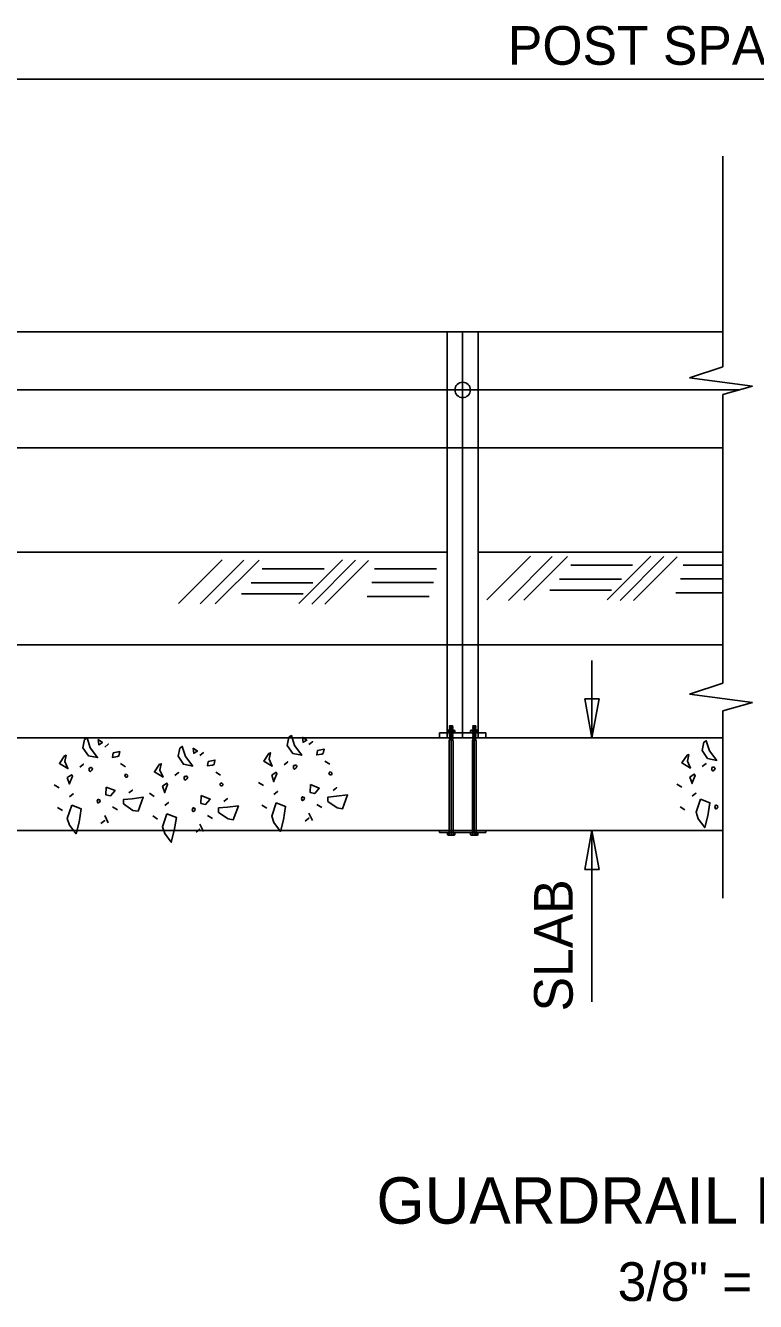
# Model space of a CAD drawing. Extents: x 0 to 90.7, y 0 to 62.8.
# Drawn here: x 18.44 to 26.31, y 29.79 to 43.55 of the extents above; entities that cross this region are included whole.
import ezdxf

# ---------------------------------------------------------------- set-up
doc = ezdxf.new("R2010")
doc.units = 0
for name, color, linetype in [('BRDG_ANNO_General-Notes', 7, 'Continuous'), ('BRDG_BASE_Ground-Lines', 7, 'Continuous'), ('BRDG_BASE_Hidden-Line', 7, 'Continuous'), ('BRDG_BASE_Obj-Line', 7, 'Continuous'), ('BRDG_BASE_Pattern', 7, 'Continuous')]:
    doc.layers.add(name, color=color, linetype=linetype)

msp = doc.modelspace()

# ---------------------------------------------------------------- linework, layer by layer
at = {"layer": 'BRDG_ANNO_General-Notes'}
for p, q in [((16.903, 42.967), (35.653, 42.967)), ((24.548, 35.866), (24.548, 36.697)), ((24.469, 36.286), (24.627, 36.286)), ((24.548, 35.866), (24.469, 36.286)), ((24.627, 36.286), (24.548, 35.866)), ((24.469, 34.446), (24.548, 34.866)), ((24.548, 33.018), (24.548, 34.866)), ((24.548, 34.866), (24.627, 34.446)), ((24.627, 34.446), (24.469, 34.446))]:
    msp.add_line(p, q, dxfattribs=at)
at = {"layer": 'BRDG_BASE_Ground-Lines'}
for p, q in [((20.559, 37.784), (20.087, 37.312)), ((20.791, 37.779), (20.32, 37.308)), ((20.957, 37.781), (20.485, 37.31)), ((21.856, 37.784), (21.385, 37.312)), ((21.996, 37.779), (21.525, 37.307)), ((22.138, 37.778), (21.667, 37.307)), ((23.886, 37.823), (23.415, 37.352)), ((24.119, 37.818), (23.647, 37.347)), ((24.284, 37.82), (23.813, 37.349)), ((24.319, 37.727), (24.985, 37.727)), ((25.184, 37.823), (24.712, 37.352)), ((25.324, 37.818), (24.852, 37.347)), ((25.466, 37.817), (24.994, 37.346)), ((25.531, 37.727), (25.958, 37.727)), ((20.991, 37.688), (21.658, 37.688)), ((22.203, 37.688), (22.87, 37.688)), ((24.198, 37.574), (24.865, 37.574)), ((25.501, 37.579), (25.958, 37.579)), ((20.871, 37.535), (21.537, 37.535)), ((22.173, 37.54), (22.84, 37.54)), ((24.093, 37.456), (24.76, 37.456)), ((25.451, 37.429), (25.958, 37.429)), ((20.766, 37.417), (21.432, 37.417)), ((22.123, 37.39), (22.79, 37.39))]:
    msp.add_line(p, q, dxfattribs=at)
at = {"layer": 'BRDG_BASE_Hidden-Line'}
for p, q in [((23.029, 35.968), (23.029, 35.917)), ((23.029, 35.948), (23.029, 35.918)), ((23.279, 35.968), (23.279, 35.917)), ((23.279, 35.948), (23.279, 35.918)), ((23.029, 34.814), (23.029, 34.844)), ((23.279, 34.814), (23.279, 34.844))]:
    msp.add_line(p, q, dxfattribs=at)
at = {"layer": 'BRDG_BASE_Obj-Line'}
for p, q in [((25.958, 39.865), (25.958, 42.137)), ((6.426, 40.241), (25.958, 40.241)), ((22.987, 40.241), (22.987, 38.991)), ((23.153, 35.866), (23.153, 40.241)), ((23.32, 40.241), (23.32, 38.991)), ((25.958, 39.865), (25.598, 39.748)), ((25.598, 39.748), (26.28, 39.657)), ((26.28, 39.657), (25.958, 39.565)), ((6.426, 39.616), (26.143, 39.616)), ((23.153, 39.616), (23.153, 39.616)), ((25.958, 36.454), (25.958, 39.565)), ((6.426, 38.991), (25.958, 38.991)), ((22.987, 35.866), (22.987, 38.991)), ((23.32, 35.866), (23.32, 38.991)), ((17.07, 37.866), (22.987, 37.866)), ((23.32, 37.866), (25.958, 37.866)), ((13.903, 36.866), (25.958, 36.866)), ((25.958, 36.454), (25.598, 36.337)), ((25.598, 36.337), (26.28, 36.247)), ((26.28, 36.247), (25.958, 36.155)), ((25.958, 34.137), (25.958, 36.155)), ((22.903, 35.918), (23.403, 35.918)), ((22.903, 35.866), (22.903, 35.918)), ((22.989, 35.92), (22.989, 35.945)), ((23.067, 35.918), (22.991, 35.918)), ((23.059, 35.948), (22.999, 35.948)), ((23.014, 35.994), (23.009, 35.991)), ((23.044, 35.994), (23.009, 35.991)), ((23.014, 35.987), (23.009, 35.991)), ((23.014, 35.987), (23.009, 35.984)), ((23.049, 35.987), (23.009, 35.984)), ((23.014, 35.981), (23.009, 35.984)), ((23.014, 35.981), (23.009, 35.977)), ((23.049, 35.981), (23.009, 35.977)), ((23.014, 35.974), (23.009, 35.977)), ((23.014, 35.974), (23.009, 35.971)), ((23.049, 35.974), (23.009, 35.971)), ((23.014, 35.968), (23.009, 35.971)), ((23.014, 35.968), (23.009, 35.964)), ((23.049, 35.968), (23.009, 35.964)), ((23.014, 35.961), (23.009, 35.964)), ((23.014, 35.961), (23.009, 35.958)), ((23.049, 35.961), (23.009, 35.958)), ((23.014, 35.954), (23.009, 35.958)), ((23.014, 35.954), (23.009, 35.951)), ((23.049, 35.954), (23.009, 35.951)), ((23.014, 35.948), (23.009, 35.951)), ((23.014, 35.948), (23.009, 35.944)), ((23.049, 35.948), (23.009, 35.944)), ((23.009, 35.918), (23.009, 35.945)), ((23.014, 35.941), (23.009, 35.944)), ((23.014, 35.941), (23.009, 35.938)), ((23.049, 35.941), (23.009, 35.938)), ((23.014, 35.935), (23.009, 35.938)), ((23.014, 35.935), (23.009, 35.931)), ((23.049, 35.935), (23.009, 35.931)), ((23.014, 35.928), (23.009, 35.931)), ((23.014, 35.928), (23.009, 35.925)), ((23.049, 35.928), (23.009, 35.925)), ((23.014, 35.921), (23.009, 35.925)), ((23.014, 35.921), (23.009, 35.918)), ((23.049, 35.921), (23.009, 35.918)), ((23.014, 35.915), (23.009, 35.918)), ((23.014, 35.915), (23.009, 35.911)), ((23.049, 35.915), (23.009, 35.911)), ((23.014, 35.908), (23.009, 35.911)), ((23.044, 35.994), (23.014, 35.994)), ((23.044, 35.991), (23.014, 35.987)), ((23.044, 35.984), (23.014, 35.981)), ((23.044, 35.977), (23.014, 35.974)), ((23.044, 35.971), (23.014, 35.968)), ((23.044, 35.964), (23.014, 35.961)), ((23.044, 35.958), (23.014, 35.954)), ((23.044, 35.951), (23.014, 35.948)), ((23.044, 35.944), (23.014, 35.941)), ((23.044, 35.938), (23.014, 35.935)), ((23.044, 35.931), (23.014, 35.928)), ((23.044, 35.925), (23.014, 35.921)), ((23.044, 35.918), (23.014, 35.915)), ((23.044, 35.911), (23.014, 35.908)), ((23.028, 34.845), (23.028, 35.918)), ((23.044, 35.994), (23.046, 35.992)), ((23.044, 35.991), (23.046, 35.992)), ((23.044, 35.991), (23.049, 35.987)), ((23.044, 35.984), (23.049, 35.987)), ((23.044, 35.984), (23.049, 35.981)), ((23.044, 35.977), (23.049, 35.981)), ((23.044, 35.977), (23.049, 35.974)), ((23.044, 35.971), (23.049, 35.974)), ((23.044, 35.971), (23.049, 35.968)), ((23.044, 35.964), (23.049, 35.968)), ((23.044, 35.964), (23.049, 35.961)), ((23.044, 35.958), (23.049, 35.961)), ((23.044, 35.958), (23.049, 35.954)), ((23.044, 35.951), (23.049, 35.954)), ((23.044, 35.951), (23.049, 35.948)), ((23.044, 35.944), (23.049, 35.948)), ((23.044, 35.944), (23.049, 35.941)), ((23.044, 35.938), (23.049, 35.941)), ((23.044, 35.938), (23.049, 35.935)), ((23.044, 35.931), (23.049, 35.935)), ((23.044, 35.931), (23.049, 35.928)), ((23.044, 35.925), (23.049, 35.928)), ((23.044, 35.925), (23.049, 35.921)), ((23.044, 35.918), (23.049, 35.921)), ((23.044, 35.918), (23.049, 35.915)), ((23.044, 35.911), (23.049, 35.915)), ((23.044, 35.911), (23.049, 35.908)), ((23.049, 35.918), (23.049, 35.945)), ((23.069, 35.92), (23.069, 35.945)), ((23.239, 35.92), (23.239, 35.945)), ((23.317, 35.918), (23.241, 35.918)), ((23.309, 35.948), (23.249, 35.948)), ((23.264, 35.994), (23.259, 35.991)), ((23.294, 35.994), (23.259, 35.991)), ((23.264, 35.987), (23.259, 35.991)), ((23.264, 35.987), (23.259, 35.984)), ((23.299, 35.987), (23.259, 35.984)), ((23.264, 35.981), (23.259, 35.984)), ((23.264, 35.981), (23.259, 35.977)), ((23.299, 35.981), (23.259, 35.977)), ((23.264, 35.974), (23.259, 35.977)), ((23.264, 35.974), (23.259, 35.971)), ((23.299, 35.974), (23.259, 35.971)), ((23.264, 35.968), (23.259, 35.971)), ((23.264, 35.968), (23.259, 35.964)), ((23.299, 35.968), (23.259, 35.964)), ((23.264, 35.961), (23.259, 35.964)), ((23.264, 35.961), (23.259, 35.958)), ((23.299, 35.961), (23.259, 35.958)), ((23.264, 35.954), (23.259, 35.958)), ((23.264, 35.954), (23.259, 35.951)), ((23.299, 35.954), (23.259, 35.951)), ((23.264, 35.948), (23.259, 35.951)), ((23.264, 35.948), (23.259, 35.944)), ((23.299, 35.948), (23.259, 35.944)), ((23.259, 35.918), (23.259, 35.945)), ((23.264, 35.941), (23.259, 35.944)), ((23.264, 35.941), (23.259, 35.938)), ((23.299, 35.941), (23.259, 35.938)), ((23.264, 35.935), (23.259, 35.938)), ((23.264, 35.935), (23.259, 35.931)), ((23.299, 35.935), (23.259, 35.931)), ((23.264, 35.928), (23.259, 35.931)), ((23.264, 35.928), (23.259, 35.925)), ((23.299, 35.928), (23.259, 35.925)), ((23.264, 35.921), (23.259, 35.925)), ((23.264, 35.921), (23.259, 35.918)), ((23.299, 35.921), (23.259, 35.918)), ((23.264, 35.915), (23.259, 35.918)), ((23.264, 35.915), (23.259, 35.911)), ((23.299, 35.915), (23.259, 35.911)), ((23.264, 35.908), (23.259, 35.911)), ((23.294, 35.994), (23.264, 35.994)), ((23.294, 35.991), (23.264, 35.987)), ((23.294, 35.984), (23.264, 35.981)), ((23.294, 35.977), (23.264, 35.974)), ((23.294, 35.971), (23.264, 35.968)), ((23.294, 35.964), (23.264, 35.961)), ((23.294, 35.958), (23.264, 35.954)), ((23.294, 35.951), (23.264, 35.948)), ((23.294, 35.944), (23.264, 35.941)), ((23.294, 35.938), (23.264, 35.935)), ((23.294, 35.931), (23.264, 35.928)), ((23.294, 35.925), (23.264, 35.921)), ((23.294, 35.918), (23.264, 35.915)), ((23.294, 35.911), (23.264, 35.908)), ((23.278, 34.845), (23.278, 35.918)), ((23.294, 35.994), (23.296, 35.992)), ((23.294, 35.991), (23.296, 35.992)), ((23.294, 35.991), (23.299, 35.987)), ((23.294, 35.984), (23.299, 35.987)), ((23.294, 35.984), (23.299, 35.981)), ((23.294, 35.977), (23.299, 35.981)), ((23.294, 35.977), (23.299, 35.974)), ((23.294, 35.971), (23.299, 35.974)), ((23.294, 35.971), (23.299, 35.968)), ((23.294, 35.964), (23.299, 35.968)), ((23.294, 35.964), (23.299, 35.961)), ((23.294, 35.958), (23.299, 35.961)), ((23.294, 35.958), (23.299, 35.954)), ((23.294, 35.951), (23.299, 35.954)), ((23.294, 35.951), (23.299, 35.948)), ((23.294, 35.944), (23.299, 35.948)), ((23.294, 35.944), (23.299, 35.941)), ((23.294, 35.938), (23.299, 35.941)), ((23.294, 35.938), (23.299, 35.935)), ((23.294, 35.931), (23.299, 35.935)), ((23.294, 35.931), (23.299, 35.928)), ((23.294, 35.925), (23.299, 35.928)), ((23.294, 35.925), (23.299, 35.921)), ((23.294, 35.918), (23.299, 35.921)), ((23.294, 35.918), (23.299, 35.915)), ((23.294, 35.911), (23.299, 35.915)), ((23.294, 35.911), (23.299, 35.908)), ((23.299, 35.918), (23.299, 35.945)), ((23.318, 35.92), (23.318, 35.945)), ((23.403, 35.866), (23.403, 35.918)), ((13.903, 35.866), (25.958, 35.866)), ((23.014, 35.908), (23.009, 35.905)), ((23.049, 35.908), (23.009, 35.905)), ((23.014, 35.902), (23.009, 35.905)), ((23.014, 35.902), (23.009, 35.898)), ((23.049, 35.902), (23.009, 35.898)), ((23.014, 35.895), (23.009, 35.898)), ((23.014, 35.895), (23.009, 35.892)), ((23.049, 35.895), (23.009, 35.892)), ((23.014, 35.888), (23.009, 35.892)), ((23.014, 35.888), (23.009, 35.885)), ((23.049, 35.888), (23.009, 35.885)), ((23.014, 35.882), (23.009, 35.885)), ((23.014, 35.882), (23.009, 35.878)), ((23.049, 35.882), (23.009, 35.878)), ((23.014, 35.875), (23.009, 35.878)), ((23.014, 35.875), (23.009, 35.872)), ((23.049, 35.875), (23.009, 35.872)), ((23.014, 35.869), (23.009, 35.872)), ((23.014, 35.869), (23.009, 35.865)), ((23.049, 35.869), (23.009, 35.865)), ((23.014, 35.862), (23.009, 35.865)), ((23.014, 35.862), (23.009, 35.859)), ((23.049, 35.862), (23.009, 35.859)), ((23.014, 35.855), (23.009, 35.859)), ((23.014, 35.855), (23.009, 35.852)), ((23.049, 35.855), (23.009, 35.852)), ((23.014, 35.849), (23.009, 35.852)), ((23.014, 35.849), (23.009, 35.845)), ((23.049, 35.849), (23.009, 35.845)), ((23.014, 35.842), (23.009, 35.845)), ((23.014, 35.842), (23.009, 35.839)), ((23.049, 35.842), (23.009, 35.839)), ((23.009, 35.839), (23.009, 34.844)), ((23.044, 35.905), (23.014, 35.902)), ((23.044, 35.898), (23.014, 35.895)), ((23.044, 35.892), (23.014, 35.888)), ((23.044, 35.885), (23.014, 35.882)), ((23.044, 35.878), (23.014, 35.875)), ((23.044, 35.872), (23.014, 35.869)), ((23.044, 35.865), (23.014, 35.862)), ((23.044, 35.859), (23.014, 35.855)), ((23.044, 35.852), (23.014, 35.849)), ((23.044, 35.845), (23.014, 35.842)), ((23.044, 35.839), (23.029, 35.837)), ((23.044, 35.905), (23.049, 35.908)), ((23.044, 35.905), (23.049, 35.902)), ((23.044, 35.898), (23.049, 35.902)), ((23.044, 35.898), (23.049, 35.895)), ((23.044, 35.892), (23.049, 35.895)), ((23.044, 35.892), (23.049, 35.888)), ((23.044, 35.885), (23.049, 35.888)), ((23.044, 35.885), (23.049, 35.882)), ((23.044, 35.878), (23.049, 35.882)), ((23.044, 35.878), (23.049, 35.875)), ((23.044, 35.872), (23.049, 35.875)), ((23.044, 35.872), (23.049, 35.869)), ((23.044, 35.865), (23.049, 35.869)), ((23.044, 35.865), (23.049, 35.862)), ((23.044, 35.859), (23.049, 35.862)), ((23.044, 35.859), (23.049, 35.855)), ((23.044, 35.852), (23.049, 35.855)), ((23.044, 35.852), (23.049, 35.849)), ((23.044, 35.845), (23.049, 35.849)), ((23.044, 35.845), (23.049, 35.842)), ((23.044, 35.839), (23.049, 35.842)), ((23.044, 35.839), (23.049, 35.836)), ((23.049, 35.836), (23.049, 34.844)), ((23.264, 35.908), (23.259, 35.905)), ((23.299, 35.908), (23.259, 35.905)), ((23.264, 35.902), (23.259, 35.905)), ((23.264, 35.902), (23.259, 35.898)), ((23.299, 35.902), (23.259, 35.898)), ((23.264, 35.895), (23.259, 35.898)), ((23.264, 35.895), (23.259, 35.892)), ((23.299, 35.895), (23.259, 35.892)), ((23.264, 35.888), (23.259, 35.892)), ((23.264, 35.888), (23.259, 35.885)), ((23.299, 35.888), (23.259, 35.885)), ((23.264, 35.882), (23.259, 35.885)), ((23.264, 35.882), (23.259, 35.878)), ((23.299, 35.882), (23.259, 35.878)), ((23.264, 35.875), (23.259, 35.878)), ((23.264, 35.875), (23.259, 35.872)), ((23.299, 35.875), (23.259, 35.872)), ((23.264, 35.869), (23.259, 35.872)), ((23.264, 35.869), (23.259, 35.865)), ((23.299, 35.869), (23.259, 35.865)), ((23.264, 35.862), (23.259, 35.865)), ((23.264, 35.862), (23.259, 35.859)), ((23.299, 35.862), (23.259, 35.859)), ((23.264, 35.855), (23.259, 35.859)), ((23.264, 35.855), (23.259, 35.852)), ((23.299, 35.855), (23.259, 35.852)), ((23.264, 35.849), (23.259, 35.852)), ((23.264, 35.849), (23.259, 35.845)), ((23.299, 35.849), (23.259, 35.845)), ((23.264, 35.842), (23.259, 35.845)), ((23.264, 35.842), (23.259, 35.839)), ((23.299, 35.842), (23.259, 35.839)), ((23.259, 35.839), (23.259, 34.844)), ((23.294, 35.905), (23.264, 35.902)), ((23.294, 35.898), (23.264, 35.895)), ((23.294, 35.892), (23.264, 35.888)), ((23.294, 35.885), (23.264, 35.882)), ((23.294, 35.878), (23.264, 35.875)), ((23.294, 35.872), (23.264, 35.869)), ((23.294, 35.865), (23.264, 35.862)), ((23.294, 35.859), (23.264, 35.855)), ((23.294, 35.852), (23.264, 35.849)), ((23.294, 35.845), (23.264, 35.842)), ((23.294, 35.839), (23.279, 35.837)), ((23.294, 35.905), (23.299, 35.908)), ((23.294, 35.905), (23.299, 35.902)), ((23.294, 35.898), (23.299, 35.902)), ((23.294, 35.898), (23.299, 35.895)), ((23.294, 35.892), (23.299, 35.895)), ((23.294, 35.892), (23.299, 35.888)), ((23.294, 35.885), (23.299, 35.888)), ((23.294, 35.885), (23.299, 35.882)), ((23.294, 35.878), (23.299, 35.882)), ((23.294, 35.878), (23.299, 35.875)), ((23.294, 35.872), (23.299, 35.875)), ((23.294, 35.872), (23.299, 35.869)), ((23.294, 35.865), (23.299, 35.869)), ((23.294, 35.865), (23.299, 35.862)), ((23.294, 35.859), (23.299, 35.862)), ((23.294, 35.859), (23.299, 35.855)), ((23.294, 35.852), (23.299, 35.855)), ((23.294, 35.852), (23.299, 35.849)), ((23.294, 35.845), (23.299, 35.849)), ((23.294, 35.845), (23.299, 35.842)), ((23.294, 35.839), (23.299, 35.842)), ((23.294, 35.839), (23.299, 35.836)), ((23.299, 35.836), (23.299, 34.844)), ((15.903, 34.866), (25.958, 34.866)), ((22.903, 34.866), (22.903, 34.845)), ((22.903, 34.845), (23.403, 34.845)), ((22.989, 34.842), (22.989, 34.818)), ((23.067, 34.844), (22.991, 34.844)), ((23.059, 34.814), (22.999, 34.814)), ((23.009, 34.844), (23.009, 34.818)), ((23.049, 34.844), (23.049, 34.818)), ((23.069, 34.842), (23.069, 34.818)), ((23.239, 34.842), (23.239, 34.818)), ((23.317, 34.844), (23.241, 34.844)), ((23.309, 34.814), (23.249, 34.814)), ((23.259, 34.844), (23.259, 34.818)), ((23.299, 34.844), (23.299, 34.818)), ((23.318, 34.842), (23.318, 34.818)), ((23.403, 34.845), (23.403, 34.866))]:
    msp.add_line(p, q, dxfattribs=at)
msp.add_circle((23.153, 39.616), 0.0833, dxfattribs=at)
for centre, radius, start, end in [((22.999, 35.933), 0.0157, 50.7833, 129.2167), ((22.991, 35.92), 0.00198, 180, 270), ((23.029, 35.893), 0.055, 68.9268, 111.0732), ((23.059, 35.933), 0.0157, 50.7833, 129.2167), ((23.067, 35.92), 0.00198, 270, 0), ((23.249, 35.933), 0.0157, 50.7833, 129.2167), ((23.241, 35.92), 0.00198, 180, 270), ((23.279, 35.893), 0.055, 68.9268, 111.0732), ((23.309, 35.933), 0.0157, 50.7833, 129.2167), ((23.316, 35.92), 0.00198, 270, 0), ((22.991, 34.842), 0.00198, 90, 180), ((22.999, 34.83), 0.0157, 230.7833, 309.2167), ((23.029, 34.869), 0.055, 248.9268, 291.0732), ((23.059, 34.83), 0.0157, 230.7833, 309.2167), ((23.067, 34.842), 0.00198, 0, 90), ((23.241, 34.842), 0.00198, 90, 180), ((23.249, 34.83), 0.0157, 230.7833, 309.2167), ((23.279, 34.869), 0.055, 248.9268, 291.0732), ((23.309, 34.83), 0.0157, 230.7833, 309.2167), ((23.316, 34.842), 0.00198, 0, 90)]:
    msp.add_arc(centre, radius, start, end, dxfattribs=at)
at = {"layer": 'BRDG_BASE_Pattern'}
for p, q in [((19.463, 35.586), (19.516, 35.553)), ((21.666, 35.612), (21.719, 35.579)), ((20.489, 35.494), (20.541, 35.461)), ((20.952, 35.384), (21.005, 35.351)), ((25.463, 35.364), (25.516, 35.331)), ((18.748, 35.358), (18.801, 35.325)), ((19.774, 35.266), (19.827, 35.233)), ((18.784, 35.114), (18.837, 35.081)), ((19.376, 35.12), (19.429, 35.087)), ((20.988, 35.14), (21.041, 35.107)), ((21.58, 35.146), (21.633, 35.113)), ((25.498, 35.12), (25.551, 35.087)), ((19.292, 35.026), (19.331, 34.947)), ((19.81, 35.022), (19.863, 34.989)), ((20.402, 35.028), (20.455, 34.995)), ((21.495, 35.052), (21.535, 34.973)), ((20.317, 34.934), (20.357, 34.855))]:
    msp.add_line(p, q, dxfattribs=at)
for points in [[(19.075, 35.846), (19.058, 35.757), (19.116, 35.671), (19.215, 35.651), (19.136, 35.756), (19.103, 35.864)], [(19.22, 35.845), (19.228, 35.79), (19.267, 35.813)], [(19.292, 35.765), (19.331, 35.797)], [(21.279, 35.872), (21.261, 35.783), (21.32, 35.697), (21.418, 35.677), (21.34, 35.782), (21.306, 35.889)], [(21.424, 35.871), (21.431, 35.816), (21.471, 35.839)], [(21.495, 35.791), (21.535, 35.823)], [(25.753, 35.816), (25.735, 35.727), (25.794, 35.64), (25.893, 35.621), (25.814, 35.725), (25.78, 35.833)], [(18.859, 35.671), (18.804, 35.588), (18.896, 35.533), (18.863, 35.608), (18.876, 35.677)], [(19.383, 35.701), (19.375, 35.654), (19.431, 35.662), (19.446, 35.67), (19.454, 35.717)], [(20.101, 35.754), (20.083, 35.666), (20.142, 35.579), (20.241, 35.559), (20.162, 35.664), (20.128, 35.772)], [(20.246, 35.753), (20.253, 35.698), (20.293, 35.722)], [(20.317, 35.673), (20.357, 35.705)], [(21.062, 35.697), (21.007, 35.614), (21.1, 35.559), (21.066, 35.634), (21.08, 35.703)], [(21.587, 35.727), (21.579, 35.68), (21.634, 35.688), (21.65, 35.696), (21.658, 35.743)], [(25.573, 35.677), (25.518, 35.594), (25.61, 35.539), (25.577, 35.614), (25.591, 35.683)], [(19.024, 35.549), (19.063, 35.581)], [(19.124, 35.539), (19.124, 35.51), (19.138, 35.5), (19.142, 35.504), (19.154, 35.516), (19.161, 35.531), (19.156, 35.539), (19.148, 35.543), (19.144, 35.543), (19.136, 35.541)], [(19.884, 35.579), (19.829, 35.497), (19.922, 35.441), (19.888, 35.516), (19.902, 35.585)], [(20.409, 35.609), (20.401, 35.562), (20.456, 35.57), (20.472, 35.578), (20.48, 35.625)], [(21.228, 35.575), (21.267, 35.607)], [(21.328, 35.565), (21.328, 35.535), (21.342, 35.526), (21.346, 35.53), (21.357, 35.542), (21.365, 35.557), (21.36, 35.565), (21.352, 35.569), (21.348, 35.569), (21.34, 35.567)], [(21.721, 35.498), (21.711, 35.477), (21.723, 35.465), (21.737, 35.465), (21.743, 35.471), (21.743, 35.483), (21.741, 35.488), (21.735, 35.494)], [(25.738, 35.555), (25.778, 35.586)], [(25.839, 35.545), (25.839, 35.515), (25.852, 35.506), (25.856, 35.51), (25.868, 35.521), (25.876, 35.537), (25.87, 35.545), (25.862, 35.549), (25.858, 35.549), (25.85, 35.547)], [(18.889, 35.436), (18.913, 35.365), (18.913, 35.373), (18.945, 35.452), (18.937, 35.467)], [(19.518, 35.472), (19.508, 35.451), (19.519, 35.439), (19.533, 35.439), (19.539, 35.445), (19.539, 35.457), (19.537, 35.462), (19.531, 35.468)], [(19.915, 35.344), (19.939, 35.273), (19.939, 35.281), (19.971, 35.36), (19.963, 35.375)], [(20.05, 35.457), (20.089, 35.489)], [(20.15, 35.447), (20.15, 35.418), (20.164, 35.408), (20.168, 35.412), (20.179, 35.424), (20.187, 35.439), (20.182, 35.447), (20.174, 35.451), (20.17, 35.451), (20.162, 35.449)], [(20.544, 35.38), (20.534, 35.359), (20.545, 35.347), (20.559, 35.347), (20.565, 35.353), (20.565, 35.365), (20.563, 35.37), (20.557, 35.377)], [(21.093, 35.462), (21.117, 35.391), (21.117, 35.399), (21.148, 35.478), (21.141, 35.493)], [(21.511, 35.36), (21.507, 35.276), (21.558, 35.264), (21.607, 35.321)], [(25.604, 35.442), (25.627, 35.371), (25.627, 35.379), (25.659, 35.458), (25.651, 35.473)], [(18.914, 35.228), (18.953, 35.26)], [(19.307, 35.334), (19.303, 35.25), (19.354, 35.238), (19.404, 35.295)], [(19.589, 35.208), (19.495, 35.2), (19.495, 35.153), (19.597, 35.082), (19.653, 35.074), (19.708, 35.223)], [(19.551, 35.27), (19.591, 35.301)], [(20.333, 35.243), (20.329, 35.158), (20.38, 35.146), (20.43, 35.203)], [(21.118, 35.254), (21.157, 35.286)], [(21.415, 35.209), (21.421, 35.189), (21.426, 35.189), (21.434, 35.191), (21.44, 35.197), (21.446, 35.209), (21.444, 35.221), (21.434, 35.223), (21.43, 35.227), (21.422, 35.227)], [(21.793, 35.234), (21.699, 35.226), (21.699, 35.179), (21.801, 35.108), (21.857, 35.1), (21.912, 35.249)], [(21.755, 35.296), (21.794, 35.327)], [(25.628, 35.234), (25.668, 35.266)], [(18.937, 35.137), (18.889, 34.995), (18.913, 34.924), (18.984, 34.83), (19.015, 34.956), (19.039, 35.098)], [(19.211, 35.183), (19.217, 35.163), (19.223, 35.163), (19.23, 35.166), (19.237, 35.171), (19.242, 35.183), (19.24, 35.195), (19.23, 35.197), (19.227, 35.201), (19.219, 35.201)], [(19.94, 35.136), (19.979, 35.168)], [(20.237, 35.091), (20.243, 35.071), (20.248, 35.071), (20.256, 35.074), (20.262, 35.079), (20.268, 35.091), (20.266, 35.103), (20.256, 35.105), (20.252, 35.109), (20.245, 35.109)], [(20.615, 35.116), (20.521, 35.108), (20.521, 35.061), (20.623, 34.99), (20.679, 34.982), (20.734, 35.131)], [(20.577, 35.178), (20.616, 35.209)], [(21.141, 35.163), (21.093, 35.021), (21.117, 34.95), (21.188, 34.856), (21.219, 34.982), (21.243, 35.124)], [(25.718, 35.203), (25.67, 35.062), (25.694, 34.991), (25.765, 34.897), (25.796, 35.022), (25.82, 35.164)], [(25.874, 35.119), (25.88, 35.099), (25.885, 35.099), (25.893, 35.102), (25.899, 35.107), (25.905, 35.119), (25.903, 35.131), (25.893, 35.133), (25.889, 35.137), (25.881, 35.137)], [(19.252, 34.941), (19.292, 34.973)], [(19.963, 35.045), (19.915, 34.903), (19.939, 34.832), (20.01, 34.738), (20.041, 34.864), (20.065, 35.006)], [(21.456, 34.967), (21.495, 34.999)], [(20.278, 34.849), (20.317, 34.881)]]:
    msp.add_lwpolyline(points, close=True, dxfattribs=at)

# ---------------------------------------------------------------- texts
at = {"layer": 'BRDG_ANNO_General-Notes'}
for s, height, p in [('POST SPACING 6\'-3"', 0.41667, (23.641, 43.122)), ('GUARDRAIL ELEVATION', 0.5, (22.223, 30.626)), ('3/8" = 1\'-0"', 0.41667, (24.825, 29.793))]:
    msp.add_text(s, height=height, dxfattribs=at).set_placement(p)
msp.add_text('SLAB', height=0.4167, rotation=90, dxfattribs=at).set_placement((24.34, 32.914))

doc.saveas('drawing.dxf')
